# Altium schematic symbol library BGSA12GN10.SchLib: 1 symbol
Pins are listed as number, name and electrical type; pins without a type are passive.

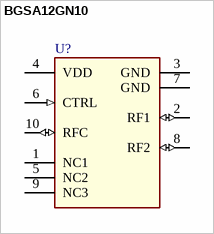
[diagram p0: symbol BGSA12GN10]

## BGSA12GN10
designator U?  (value not drawn)
Low COFF Dual-Pole Single Throw Antenna Tuning Switch; Manufacturer: Infineon Technologies
footprint INF-PG-TSNP10-1
pins: 1 NC1 "Not Connected", 2 RF1 (io), 3 GND (power) "Ground", 4 VDD (power) "Supply Voltage", 5 NC2 "Not Connected", 6 CTRL (in) "Control Pin", 7 GND (power) "Ground", 8 RF2 (io), 9 NC3 "Not Connected", 10 RFC (io) "Common RF"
